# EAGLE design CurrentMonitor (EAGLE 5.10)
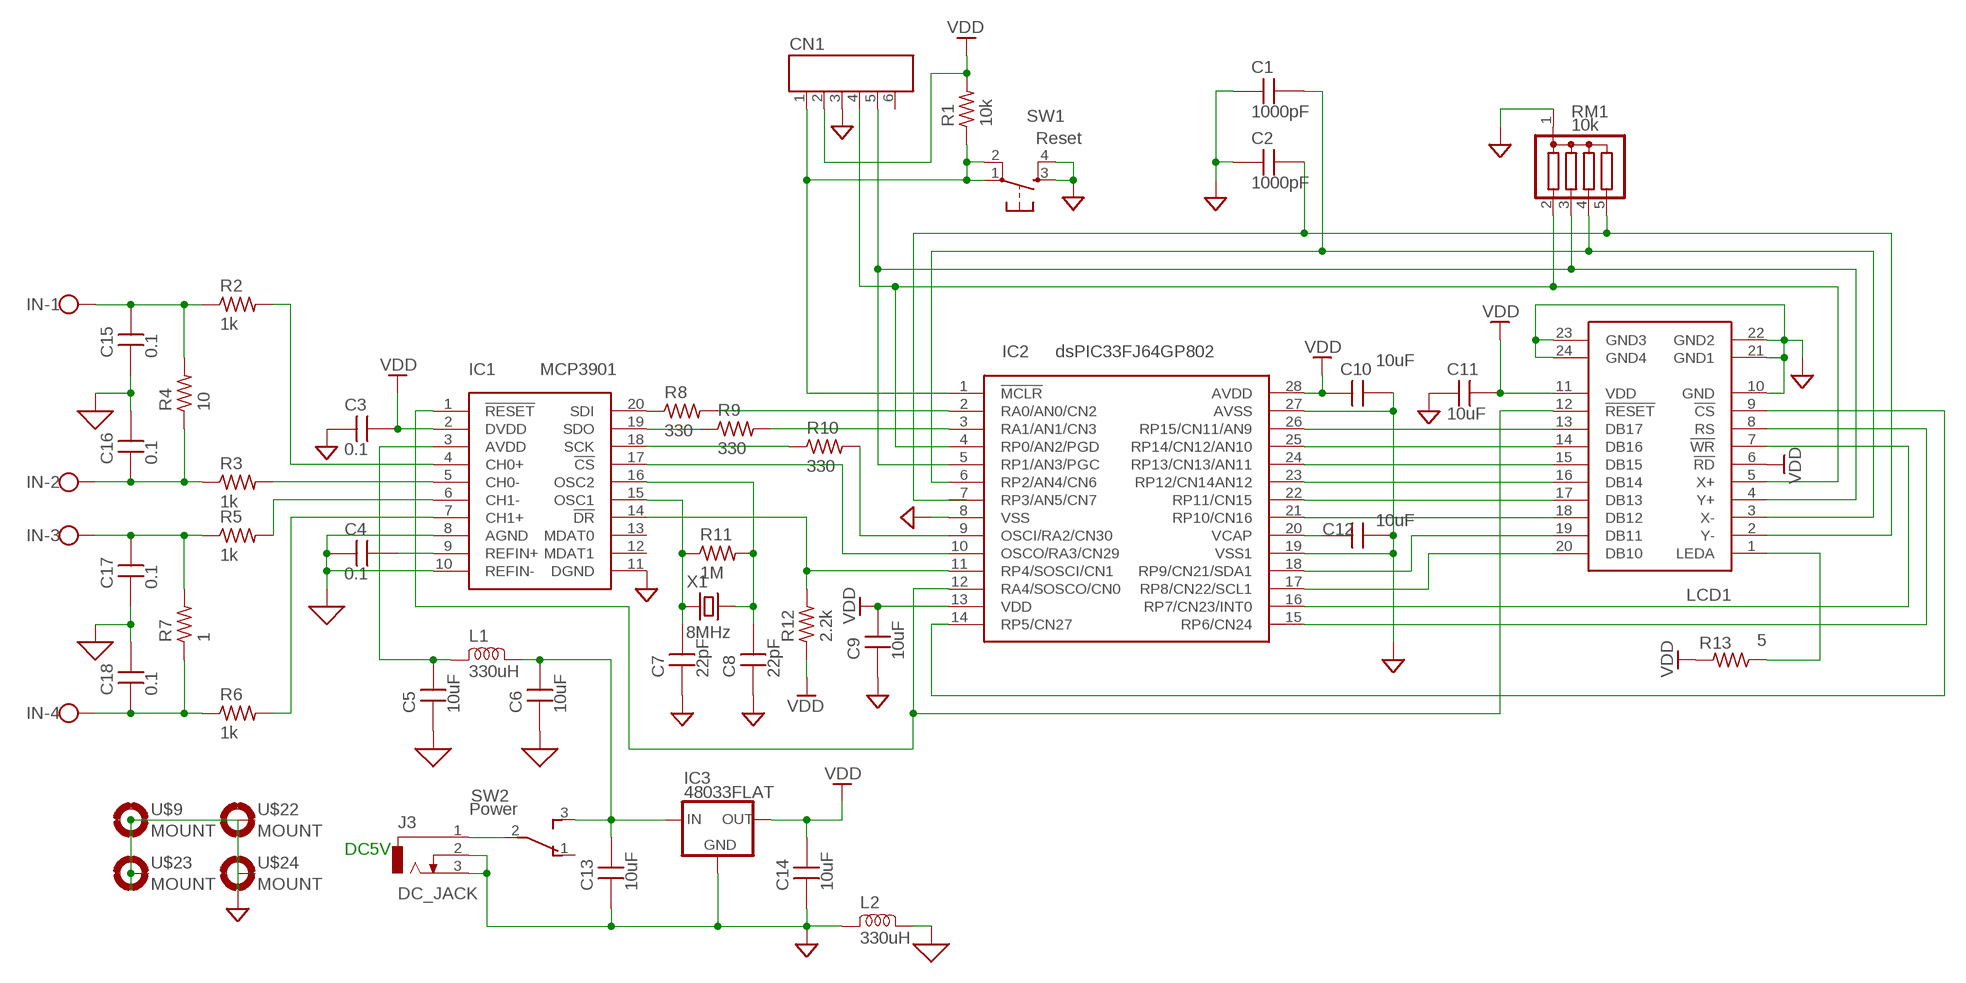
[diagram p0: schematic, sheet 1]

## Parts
C1  1000pF  CAPDIP_2  [CAP_DIP_2]
C2  1000pF  CAPDIP_2  [CAP_DIP_2]
C3  0.1  CAPSM3216  [C3216]
C4  0.1  CAPSM3216  [C3216]
C5  10uF  CAPSM3216  [C3216]
C6  10uF  CAPSM3216  [C3216]
C7  22pF  CAPDIP_1  [CAP_DIP_1]
C8  22pF  CAPDIP_1  [CAP_DIP_1]
C9  10uF  CAPSM3216  [C3216]
C10  10uF  CAPSM3216  [C3216]
C11  10uF  CAPSM3216  [C3216]
C12  10uF  CAPSM3216  [C3216]
C13  10uF  CAPSM3225  [C3225]
C14  10uF  CAPSM3225  [C3225]
C15  0.1  CAPSM3216  [C3216]
C16  0.1  CAPSM3216  [C3216]
C17  0.1  CAPSM3216  [C3216]
C18  0.1  CAPSM3216  [C3216]
CN1  CON_6P  [CON_HRS_DIP_6]
IC1  MCP3901  MCP3901A0  [SSOP20]
IC2  dsPIC33FJ64GP802  DSPIC33FJ64GP802  [DIL28-3]
IC3  48033FLAT  7803FLAT  [TO252]
IN  W237-4  [W237-4]
J3  DC_JACK  [DCJ0202]
L1  330uH  L-SMALL  [MICRO_INDUCTOR]
L2  330uH  L-SMALL  [MICRO_INDUCTOR]
LCD1  LCD_EGO028Q02BRD  [LCD_EGO028Q02BRD]
R1  10k  R0.125W_2P  [R_0.125W_2]
R2  1k  R0.125W_2P  [R_0.125W_2]
R3  1k  R0.125W_2P  [R_0.125W_2]
R4  10  R0.125W_2P  [R_0.125W_2]
R5  1k  R0.125W_2P  [R_0.125W_2]
R6  1k  R0.125W_2P  [R_0.125W_2]
R7  1  R0.125W_2P  [R_0.125W_2]
R8  330  R0.125W_2P  [R_0.125W_2]
R9  330  R0.125W_2P  [R_0.125W_2]
R10  330  R0.125W_2P  [R_0.125W_2]
R11  1M  R0.125W_2P  [R_0.125W_2]
R12  2.2k  R0.125W_2P  [R_0.125W_2]
R13  5  R0.125W_2P  [R_0.125W_2]
RM1  10k  RM4  [SIL5]
SW1  Reset  TACT-SW  [B3F-10X]
SW2  Power  SLIDESW-3  [DS-3]
U$9  MOUNT  MOUNT-PAD2.1  [PAD-2.1]
U$22  MOUNT  MOUNT-PAD2.1  [PAD-2.1]
U$23  MOUNT  MOUNT-PAD2.1  [PAD-2.1]
U$24  MOUNT  MOUNT-PAD2.1  [PAD-2.1]
X1  8MHz  XTAL49S  [HC49/S]

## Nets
AGND: C4.1 C5.1 C6.1 C15.1 C16.2 C17.1 C18.2 IC1.8(AGND) IC1.10(REFIN-) L2.2
GND: C1.1 C2.1 C3.1 C7.1 C8.1 C9.1 C10.2 C11.1 C12.2 C13.1 C14.1 CN1.3 IC1.11(DGND) IC2.8(VSS) IC2.19(VSS1) IC2.27(AVSS) IC3.3(GND) J3.2 J3.3 L2.1 LCD1.10(GND) LCD1.21(GND1) LCD1.22(GND2) LCD1.23(GND3) LCD1.24(GND4) RM1.1 SW1.3(S) SW1.4(S1) U$9.B2,1(MOUNT) U$22.B2,1(MOUNT) U$23.B2,1(MOUNT) U$24.B2,1(MOUNT)
N$1: IC2.26(RP15/CN11/AN9) LCD1.13(DB17)
N$2: IC2.25(RP14/CN12/AN10) LCD1.14(DB16)
N$3: IC2.24(RP13/CN13/AN11) LCD1.15(DB15)
N$4: IC2.23(RP12/CN14AN12) LCD1.16(DB14)
N$5: IC2.22(RP11/CN15) LCD1.17(DB13)
N$6: IC2.21(RP10/CN16) LCD1.18(DB12)
N$7: IC2.18(RP9/CN21/SDA1) LCD1.19(DB11)
N$8: IC1.20(SDI) R8.1
N$9: IC2.16(RP7/CN23/INT0) LCD1.7(!WR)
N$10: C1.2 IC2.6(RP2/AN4/CN6) LCD1.3(X-) RM1.4
N$11: IC2.14(RP5/CN27) LCD1.9(!CS)
N$12: IC2.15(RP6/CN24) LCD1.8(RS)
N$13: LCD1.1(LEDA) R13.1
N$14: CN1.1 IC2.1(!MCLR) R1.1 SW1.1(P) SW1.2(P1)
N$15: IC1.1(!RESET) IC2.12(RA4/SOSCO/CN0) LCD1.12(!RESET)
N$16: IC2.2(RA0/AN0/CN2) R8.2
N$17: IC2.9(OSCI/RA2/CN30) R10.2
N$18: J3.1 SW2.2(P)
N$19: IC1.17(!CS) IC2.10(OSCO/RA3/CN29)
N$20: IC1.14(!DR) IC2.11(RP4/SOSCI/CN1) R12.2
N$21: C5.2 IC1.3(AVDD) L1.1
N$22: C4.2 IC1.9(REFIN+)
N$23: CN1.4 IC2.4(RP0/AN2/PGD) LCD1.5(X+) RM1.2
N$24: C12.1 IC2.20(VCAP)
N$25: IC1.4(CH0+) R2.2
N$26: IC1.5(CH0-) R3.2
N$27: C2.2 IC2.7(RP3/AN5/CN7) LCD1.2(Y-) RM1.5
N$28: C16.1 IN.2 R3.1 R4.1
N$29: C6.2 C13.2 IC3.1(IN) L1.2 SW2.3(S)
N$30: IC2.17(RP8/CN22/SCL1) LCD1.20(DB10)
N$31: C15.2 IN.1 R2.1 R4.2
N$32: IC1.6(CH1-) R5.2
N$33: C17.2 IN.3 R5.1 R7.2
N$34: IC1.7(CH1+) R6.2
N$35: C18.1 IN.4 R6.1 R7.1
N$36: C7.2 IC1.15(OSC1) R11.1 X1.1
N$37: C8.2 IC1.16(OSC2) R11.2 X1.2
N$38: IC1.19(SDO) R9.1
N$39: CN1.5 IC2.5(RP1/AN3/PGC) LCD1.4(Y+) RM1.3
N$40: IC2.3(RA1/AN1/CN3) R9.2
N$41: IC1.18(SCK) R10.1
VDD: C3.2 C9.2 C10.1 C11.2 C14.2 CN1.2 IC1.2(DVDD) IC2.13(VDD) IC2.28(AVDD) IC3.2(OUT) LCD1.6(!RD) LCD1.11(VDD) R1.2 R12.1 R13.2
Unconnected: CN1.6 IC1.12(MDAT1) IC1.13(MDAT0) SW2.1(O)

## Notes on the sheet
- DC5V

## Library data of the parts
C1-C18 = MyLib:CAP: Non polar capacitor
CN1 = MyLib:CON_6P: 6P Molex Connector
IC1 = microchip-dspic:MCP3901: 16/24bit Delat Sigma A/D Convertor
IC2 = microchip-dspic:DSPIC33FJ64GP802: dsPIC33 RAM16K CAN
IC3 = MyLib:78*
IN = con-wago-500:W237-4: WAGO SCREW CLAMP
J3 = MyLib:DC_JACK: DC Jack with Switch
L1 L2 = MyLib:L: RF Chork Coil
LCD1 = MyLib:LCD_EGO028Q02BRD: 2.8" Color LCD Board with Touch Sensor
R1-R13 = MyLib:R: General Resiter 1/8W 1/4W 1/2W V/H
RM1 = MyLib:RM4: 4 Element Register Array Module
SW1 = MyLib:TACT-SW: Tacticle Push Switch
SW2 = MyLib:SLIDESW-3: 3P Slide Switch
U$9 U$22-U$24 = MyLib:MOUNT-PAD: 2.1mm Mount Pad (Connectable to GND)
X1 = MyLib:XTAL: Crystal Oscillator HC49U/S

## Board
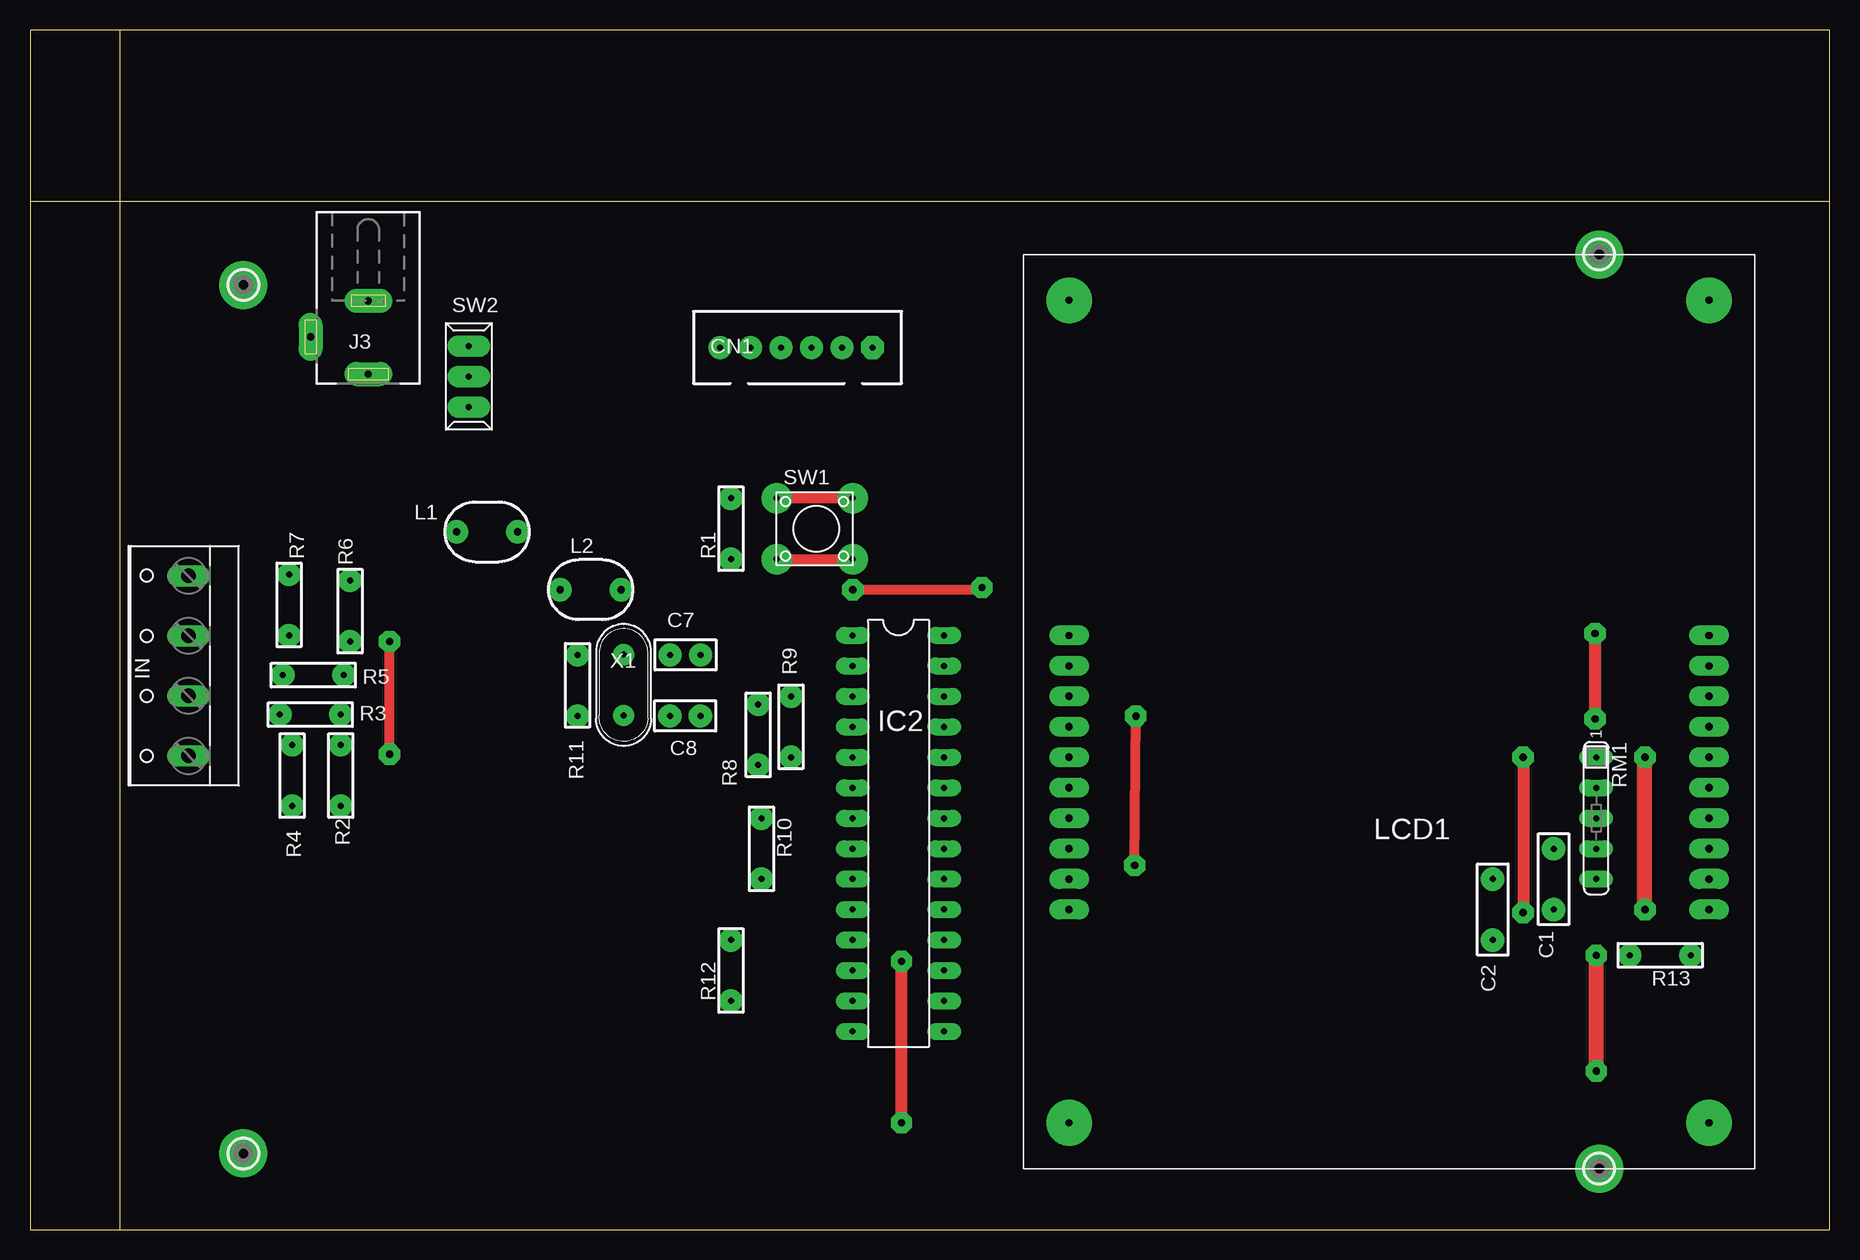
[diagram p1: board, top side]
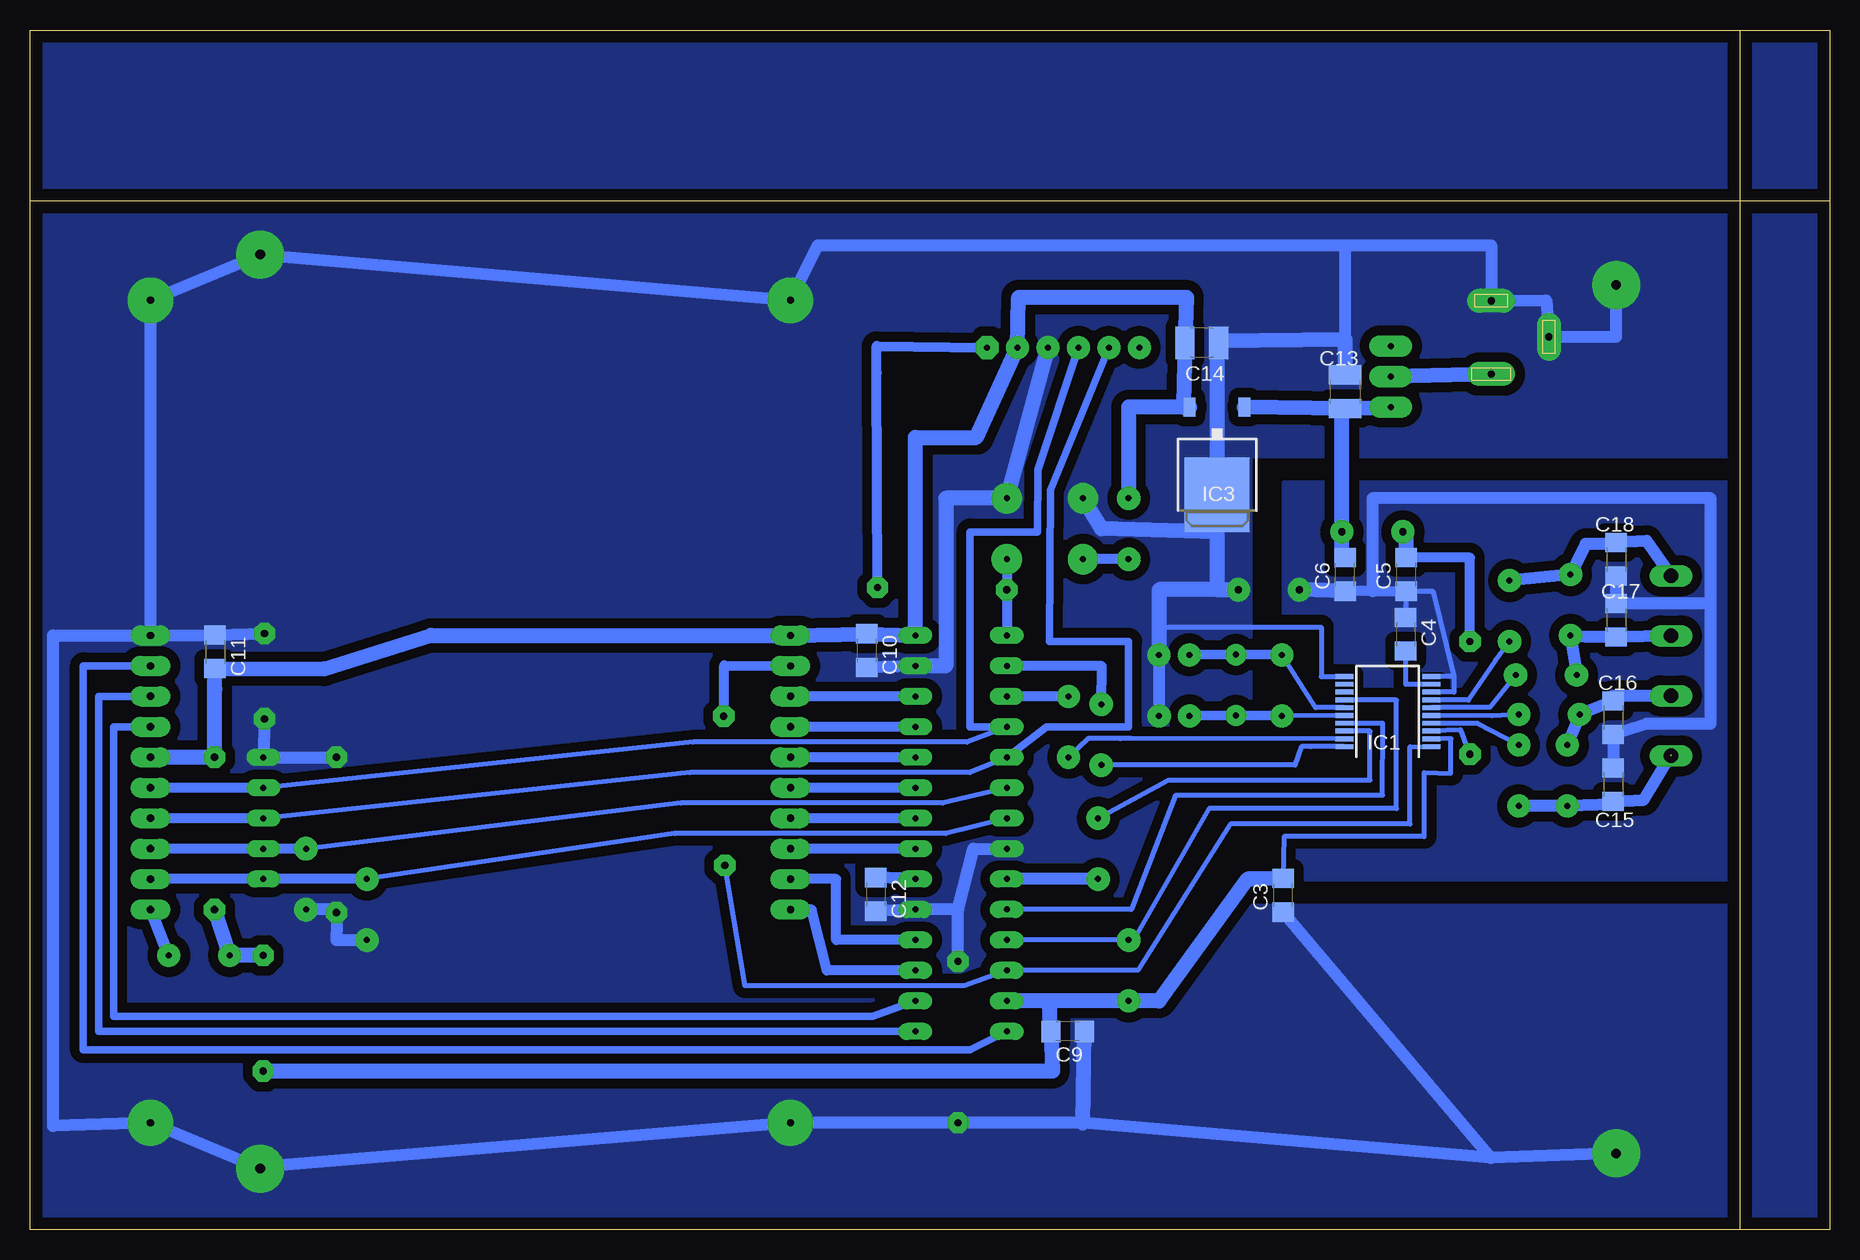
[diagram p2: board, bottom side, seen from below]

Size 150 x 100 mm. Coordinates in mm from the lower left corner, seen from the top.
Outline: 7.46,0 0,0 0,85.73
Outline: 7.46,0 150,0 150,85.73
Outline: 150,85.73 150,100 7.46,100
Outline: 0,85.73 0,100 7.46,100
Outline: 7.46,100 7.46,0
Outline: 0,85.73 150,85.73
Copper layers (1*16): Top 0.035mm / dielectric 1.5mm / Bottom 0.035mm
Design rules "default": minimum track width 10mil, minimum drill 24mil, track to track 8mil, track to pad 8mil, pad to pad 8mil, via to via 8mil, smd to smd 8mil, copper to edge 40mil, drill to drill 8mil, minimum pad ring 10mil, minimum via ring 8mil, stop-mask expansion 4mil, vias tented up to drill 0mil, thermal gap 10mil

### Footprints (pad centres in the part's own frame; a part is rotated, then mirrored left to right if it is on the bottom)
CAP_DIP_2 = drill 0.5 pad 1.93 round: 1 -2.54,0; 2 2.54,0
C3216 = smd 1.6 x 1.8: 1 -1.4,0; 2 1.4,0
CAP_DIP_1 = drill 0.5 pad 1.93 round: 1 -1.27,0; 2 1.27,0
C3225 = smd 1.6 x 2.7: 1 -1.4,0; 2 1.4,0
CON_HRS_DIP_6 = drill 0.5 pad 1.93 octagon: 1 -6.35,0 | drill 0.5 pad 1.93 round: 2 -3.81,0; 3 -1.27,0; 4 1.27,0; 5 3.81,0; 6 6.35,0
SSOP20 = smd 0.4 x 1.5: 1 -2.925,-3.625; 2 -2.275,-3.625; 3 -1.625,-3.625; 4 -0.975,-3.625; 5 -0.325,-3.625; 6 0.325,-3.625; 7 0.975,-3.625; 8 1.625,-3.625; 9 2.275,-3.625; 10 2.925,-3.625; 11 2.925,3.625; 12 2.275,3.625; 13 1.625,3.625; 14 0.975,3.625; 15 0.325,3.625; 16 -0.325,3.625; 17 -0.975,3.625; 18 -1.625,3.625; 19 -2.275,3.625; 20 -2.925,3.625
DIL28-3 = drill 0.5 pad 1.422 long: 1 -16.51,-3.81; 2 -13.97,-3.81; 3 -11.43,-3.81; 4 -8.89,-3.81; 5 -6.35,-3.81; 6 -3.81,-3.81; 7 -1.27,-3.81; 8 1.27,-3.81; 9 3.81,-3.81; 10 6.35,-3.81; 11 8.89,-3.81; 12 11.43,-3.81; 13 13.97,-3.81; 14 16.51,-3.81; 15 16.51,3.81; 16 13.97,3.81; 17 11.43,3.81; 18 8.89,3.81; 19 6.35,3.81; 20 3.81,3.81; 21 1.27,3.81; 22 -1.27,3.81; 23 -3.81,3.81; 24 -6.35,3.81; 25 -8.89,3.81; 26 -11.43,3.81; 27 -13.97,3.81; 28 -16.51,3.81
TO252 = smd 1 x 1.6: 1 -2.28,-4.8; 2 2.28,-4.8 | smd 5.4 x 6.2: 3 0,2.5
W237-4 = drill 1.194 long: 1 -7.5,-1.27; 2 -2.5,-1.27; 3 2.5,-1.27; 4 7.5,-1.27
DCJ0202 = drill 0.6 pad 2 long: 1 0,6.148; 2 4.8,3.048; 3 0,0.048
MICRO_INDUCTOR = drill 0.6 pad 1.93 round: 1 -2.54,0; 2 2.54,0
LCD_EGO028Q02BRD = drill 0.6 pad 1.676 long: 1 -25.4,17.78; 2 -25.4,15.24; 3 -25.4,12.7; 4 -25.4,10.16; 5 -25.4,7.62; 6 -25.4,5.08; 7 -25.4,2.54; 8 -25.4,0; 9 -25.4,-2.54; 10 -25.4,-5.08; 11 27.94,-5.08; 12 27.94,-2.54; 13 27.94,0; 14 27.94,2.54; 15 27.94,5.08; 16 27.94,7.62; 17 27.94,10.16; 18 27.94,12.7; 19 27.94,15.24; 20 27.94,17.78 | drill 0.6 pad 3.81 round: 21 -25.4,-33.02; 22 27.94,-33.02; 23 27.94,35.56; 24 -25.4,35.56
R_0.125W_2 = drill 0.5 pad 1.93 round: 1 -2.54,0; 2 2.54,0
SIL5 = drill 0.5 pad 1.422 long: 1 -5.08,0; 2 -2.54,0; 3 0,0; 4 2.54,0; 5 5.08,0
B3F-10X = drill 0.5 pad 2.54 round: 1 -1.27,2.54; 2 5.08,2.54; 3 -1.27,-2.54; 4 5.08,-2.54
DS-3 = drill 0.5 pad 1.778 long: 1 0,-2.54; 2 0,0; 3 0,2.54
PAD-2.1 = drill 0.8 pad 4 round: B2,1 0,0
HC49/S = drill 0.5 pad 1.778 round: 1 -2.54,0; 2 2.54,0

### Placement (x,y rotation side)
C1  127,29.21 90 top
C2  121.92,26.67 90 top
C3  45.54,27.86 90 bottom
C4  35.33,49.63 270 bottom
C5  35.28,54.61 90 bottom
C6  40.39,54.61 90 bottom
C7  54.64,47.9 180 top
C8  54.61,42.82 180 top
C9  63.5,16.51 180 bottom
C10  80.26,48.26 270 bottom
C11  134.57,48.16 270 bottom
C12  79.5,27.94 270 bottom
C13  40.39,69.85 270 bottom
C14  52.32,73.91 180 bottom
C15  18.03,37.08 270 bottom
C16  18.03,42.67 270 bottom
C17  17.78,50.8 270 bottom
C18  17.78,55.88 270 bottom
CN1  63.88,73.53 180 top
IC1  36.83,43.18 90 bottom
IC2  72.39,33.02 270 top
IC3  51.05,63.75 180 bottom
IN  11.94,46.99 90 top
J3  28.19,77.47 180 top
L1  38.1,58.17 0 top
L2  46.74,53.34 180 top
LCD1  114.55,44.45 180 top
R1  58.42,58.42 90 top
R2  25.91,37.85 90 top
R3  23.37,42.93 0 top
R4  21.84,37.85 270 top
R5  23.62,46.23 0 top
R6  26.67,51.56 270 top
R7  21.59,52.07 270 top
R8  60.71,41.25 90 top
R9  63.42,41.91 90 top
R10  60.96,31.75 270 top
R11  45.64,45.36 270 top
R12  58.42,21.59 90 top
R13  135.89,22.86 180 top
RM1  130.56,34.29 270 top
SW1  67.31,58.42 180 top
SW2  36.58,71.12 180 top
U$9  130.81,81.28 0 top
U$22  17.78,6.35 0 top
U$23  130.81,5.08 0 top
U$24  17.78,78.74 0 top
X1  49.48,45.39 270 top

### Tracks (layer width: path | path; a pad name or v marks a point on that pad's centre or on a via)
AGND
  Bottom 0.406: IC1.8 31.29,44.81 31.29,46.1 | 31.29,46.1 IC1.10 | 31.29,46.1 33.07,53.21 C5.1 35.33,52.02 C4.1
  Bottom 0.813: C5.1 38.1,53.21 C6.1
  Bottom 1.016: C18.2 C17.1 9.91,52.2 | C15.1 C16.2 15.24,42.16 9.91,42.16 9.91,52.2 | 9.91,52.2 9.91,60.96 38.1,60.96 38.1,53.21
  Bottom 1.27: C6.1 L2.2
  pour Bottom (isolate 0.813, no thermals): 7.11,62.23 45.47,62.23 45.47,29.21 7.11,29.21
GND  (via drill 0.6 pad 1.78)
  Top 0.813: SW1.4 SW1.3
  Top 1.016: v130.45,49.68 v130.45,42.57 | v124.46,39.37 v124.46,26.42 | v72.64,8.89 v72.64,22.35
  Bottom 0.406: IC1.11 42.37,46.1 42.37,50.22 55.88,50.22 C7.1
  Bottom 1.016: C7.1 C8.1 | C12.2 IC2.19 72.64,26.67 | IC2.27 C10.2 | IC2.8 71.37,31.75 72.64,26.67 | LCD1.10 C11.1 v130.45,49.68 | v130.45,42.57 RM1.1 v124.46,39.37 | v124.46,26.42 124.41,26.69 | 124.41,26.69 C1.1 | C2.1 124.46,24.13 124.41,26.69 | LCD1.10 148.08,49.53 148.08,8.64 LCD1.24 131.04,5.18 | 131.04,5.18 U$23.B2,1 | 131.04,5.18 LCD1.23 v72.64,8.89 62.23,8.89 28.23,5.97 | U$22.B2,1 28.23,5.97 | LCD1.10 LCD1.21 U$9.B2,1 LCD1.22 84.33,82.04 40.39,82.04 | 40.39,82.04 40.39,74.17 | U$24.B2,1 17.78,74.42 J3.2 23.62,77.47 J3.3 28.19,82.04 40.39,82.04 | 28.23,5.97 C3.1 | v72.64,22.35 72.64,26.67
  Bottom 1.27: CN1.3 SW1.3 73.66,60.96 73.66,46.99 IC2.27 | C13.1 40.39,74.17 51.06,74.07 IC3.3 51.05,58.17 | 51.05,58.17 51.05,53.34 | C7.1 55.88,53.34 51.05,53.34 | SW1.4 60.71,58.42 51.05,58.17 | 62.23,8.89 C9.1 | 51.05,53.34 L2.1
  pour Bottom (isolate 0.813, no thermals): 7.11,85.85 150.11,85.85 150.11,-0.25 7.11,-0.25 7.11,26.92 48.26,26.92 48.26,64.52 7.11,64.52
N$1
  Bottom 0.813: IC2.26 LCD1.13
N$2
  Bottom 0.813: IC2.25 LCD1.14
N$3
  Bottom 0.813: IC2.24 LCD1.15
N$4
  Bottom 0.813: IC2.23 LCD1.16
N$5
  Bottom 0.813: IC2.22 LCD1.17
N$6
  Bottom 0.813: IC2.21 LCD1.18
N$7
  Bottom 0.813: IC2.18 82.8,24.13 82.8,29.21 LCD1.19
N$8
  Bottom 0.406: IC1.20 43.26,40.26 44.02,40.26 44.55,38.71 R8.1
N$9
  Bottom 0.61: IC2.16 79.76,17.78 143,17.78 143,41.91 LCD1.7
N$10
  Bottom 0.406: IC2.6 73.91,35.56 95.76,35.56 C1.2
  Bottom 0.813: LCD1.3 RM1.4 C1.2
N$11
  Bottom 0.61: IC2.14 71.63,14.99 145.54,14.99 145.54,46.99 LCD1.9
N$12
  Bottom 0.61: IC2.15 144.27,16.51 144.27,44.45 LCD1.8
N$13
  Bottom 1.016: R13.1 LCD1.1
N$14  (via drill 0.6 pad 1.78)
  Top 0.813: SW1.2 SW1.1 | v68.58,53.34 79.25,53.34 v79.35,53.52
  Bottom 0.813: R1.1 SW1.2 | SW1.1 v68.58,53.34 IC2.1 | v79.35,53.52 79.43,71.42 79.43,73.66 CN1.1
N$15  (via drill 0.6 pad 1.78)
  Top 0.813: v92.08,30.35 v92.18,42.8
  Bottom 0.406: IC1.1 34.98,40.23 34.98,33.81 49.94,33.81 57.66,21.61 IC2.12 72.14,20.32 90.4,20.32 v92.08,30.35 | v92.18,42.8 92.13,42.8
  Bottom 0.813: 92.13,42.8 92.13,47.04 LCD1.12
N$16
  Bottom 0.813: R8.2 60.66,46.97 IC2.2
N$17
  Bottom 1.016: R10.2 IC2.9
N$18
  Bottom 1.27: J3.1 SW2.2
N$19
  Bottom 0.406: IC1.17 37.24,42.19 37.26,36.2 54.53,36.17 58.19,26.67 IC2.10
N$20
  Bottom 0.406: IC1.14 40.64,44.15 36.09,44.15 36.09,35.1 51.71,35.1 58.06,24.08 58.42,24.08 R12.2 IC2.11 68.58,24.08
N$21  (via drill 0.6 pad 1.78)
  Top 0.813: v29.97,39.62 v29.97,49.02
  Bottom 0.406: v29.97,39.62 30.73,41.66 IC1.3
  Bottom 0.813: C5.2 29.97,56.01 v29.97,49.02
  Bottom 1.27: L1.1 35.28,58.17 C5.2
N$22
  Bottom 0.406: IC1.9 35.33,45.44 C4.2
N$23
  Bottom 0.406: IC2.4 71.88,40.64 94.74,40.64 RM1.2
  Bottom 0.61: IC2.4 71.63,41.91 71.63,58.17 66.04,58.17 65.99,63.37 CN1.4
  Bottom 0.813: RM1.2 LCD1.5
N$24
  Bottom 1.016: IC2.20 C12.1
N$25
  Bottom 0.406: IC1.4 29.34,42.19 R2.2
N$26
  Bottom 0.406: IC1.5 28.12,42.82 R3.2
N$27
  Bottom 0.406: IC2.7 73.66,33.02 96.27,33.02 C2.2
  Bottom 0.813: LCD1.2 RM1.5 C2.2
N$28
  Bottom 1.016: R4.1 R3.1 C16.1 | C16.1 18.03,44.2 | IN.2 18.03,44.49 C16.1
N$29
  Bottom 1.27: C13.2 SW2.3 | C13.2 IC3.1 | C6.2 40.64,56.01 L1.2 40.64,68.45 C13.2
N$30
  Bottom 0.813: IC2.17 83.57,21.59 84.84,26.67 LCD1.20
N$31  (1 unrouted)
  Bottom 1.016: R2.1 R4.2 18.03,35.43 C15.2 15.49,35.81 13.21,39.62
N$32
  Bottom 0.406: IC1.6 28.3,43.54 R5.2
N$33
  Bottom 1.016: R5.1 R7.2 20.32,49.4 C17.2 | C17.2 17.78,49.53 | IN.3 C17.2
N$34
  Bottom 0.406: IC1.7 30.1,44.15 27.81,47.5 R6.2
N$35
  Bottom 1.016: R6.1 R7.1 20.32,57.15 17.78,57.15 C18.1 15.24,57.4 IN.4
N$36
  Bottom 0.406: IC1.15 42.85,43.51 R11.1
  Bottom 0.813: R11.1 X1.1 C7.2
N$37
  Bottom 0.406: IC1.16 R11.2
  Bottom 0.813: R11.2 X1.2 C8.2
N$38
  Bottom 0.406: IC1.19 58.27,40.95 59.11,40.92 61.77,40.92 R9.1
N$39
  Bottom 0.406: IC2.5 71.63,38.1 95,38.1 RM1.3
  Bottom 0.61: CN1.5 64.92,61.65 65.02,49.02 58.42,49.02 58.42,41.91 65.28,41.91 IC2.5
  Bottom 0.813: RM1.3 LCD1.4
N$40
  Bottom 0.813: R9.2 IC2.3
N$41
  Bottom 0.406: IC1.18 38.3,41.55 38.3,37.44 55.14,37.44 R10.1
N$42
  pour Bottom (isolate 0.813, no thermals): 0,100.33 7.87,100.33 7.87,0 0,0
N$43
  pour Bottom (isolate 0.813, no thermals): 0,100.33 149.86,100.33 149.86,85.09 0,85.09
VDD  (via drill 0.6 pad 1.78)
  Top 1.27: v134.62,26.67 v134.62,39.37 | v130.56,13.21 v130.56,22.86
  Bottom 0.406: IC1.2 31.55,40.92 31.57,38.02 33.78,38.1 33.78,32.77 45.47,32.77 C3.2
  Bottom 1.016: C9.2 65.02,18.54 65.02,19.05
  Bottom 1.27: 65.02,18.54 65.02,16.51 | IC2.13 65.02,19.05 R12.1 55.88,19.05 48.51,29.21 48.26,29.21 C3.2 | R1.2 58.42,68.58 57.91,68.58 IC3.2 53.85,68.55 53.85,68.83 C14.2 53.59,77.72 67.59,77.72 CN1.2 71.12,66.04 76.2,66.04 IC2.28 C10.1 LCD1.11 116.59,49.53 125.48,46.74 C11.2 134.59,45.03 v134.62,39.37 LCD1.6 | v134.62,26.67 R13.2 v130.56,22.86 | v130.56,13.21 64.77,13.21 C9.2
